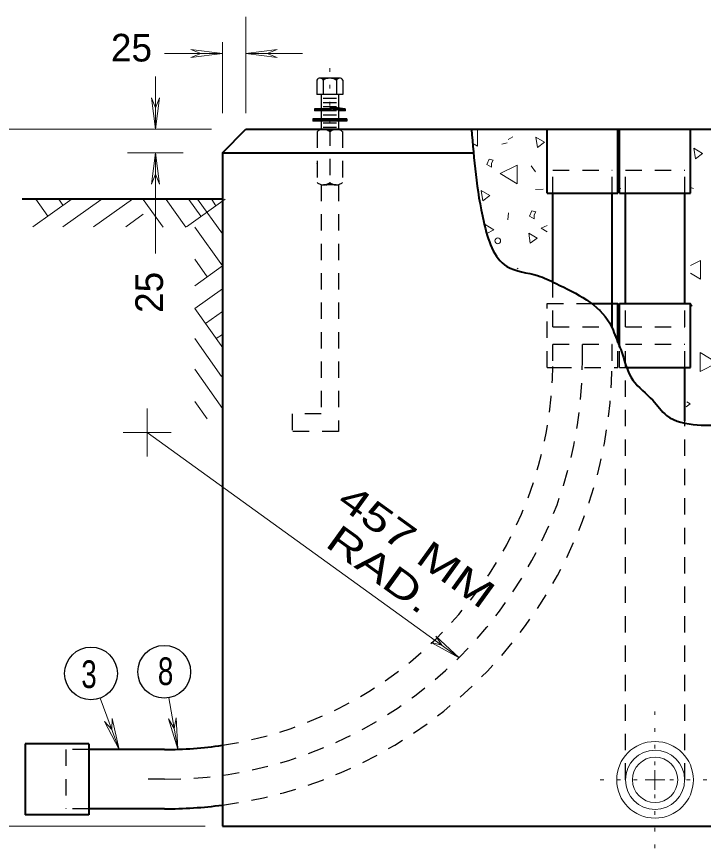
# Model space of a CAD drawing. Extents: x 312583 to 312854, y 144419 to 144597.
# Drawn here: x 312734.56 to 312753.44, y 144519.54 to 144542.49 of the extents above; entities that cross this region are included whole.
import ezdxf

# ---------------------------------------------------------------- set-up
doc = ezdxf.new("R2010")
doc.units = 0
doc.header["$LTSCALE"] = 0.3
doc.linetypes.add('DOTTED', pattern=[1.5, 0.3, -1.2])
doc.linetypes.add('SHORT_DASHED', pattern=[2.7, 1.5, -1.2])
doc.layers.add('1', color=7, linetype='Continuous', lineweight=25)
doc.layers.add('2', color=7, linetype='Continuous', lineweight=13)

msp = doc.modelspace()

# ---------------------------------------------------------------- linework, layer by layer
at = {"layer": '1', "linetype": 'DOTTED', "lineweight": 13}
msp.add_line((312743.1754, 144541.0728), (312743.1754, 144539.3938), dxfattribs=at)
at = {"layer": '1'}
for p, q in [((312742.815, 144540.7431), (312742.815, 144540.3521)), ((312743.4437, 144540.8044), (312742.907, 144540.8044)), ((312742.9914, 144540.7431), (312742.9914, 144540.3521)), ((312743.3517, 144540.7431), (312743.3517, 144540.3521)), ((312743.528, 144540.7431), (312743.528, 144540.3521)), ((312743.528, 144540.3521), (312742.815, 144540.3521)), ((312742.93, 144540.3521), (312742.93, 144539.3938)), ((312743.3517, 144540.2371), (312742.9914, 144540.2371)), ((312743.413, 144540.3521), (312743.413, 144539.3938)), ((312743.3517, 144540.1221), (312742.9914, 144540.1221)), ((312743.3517, 144540.0148), (312742.9914, 144540.0148)), ((312742.7537, 144539.9534), (312742.7537, 144539.8998)), ((312743.1907, 144539.9534), (312742.7537, 144539.9534)), ((312743.206, 144539.8998), (312742.7537, 144539.8998)), ((312743.3517, 144539.8998), (312742.9914, 144539.8998)), ((312743.3517, 144539.7848), (312742.9914, 144539.7848)), ((312743.5894, 144539.9534), (312743.5894, 144539.8998)), ((312743.643, 144539.6774), (312742.7, 144539.6774)), ((312742.7, 144539.6774), (312742.7, 144539.6161)), ((312743.643, 144539.6621), (312742.7, 144539.6621)), ((312743.643, 144539.6468), (312742.7, 144539.6468)), ((312743.643, 144539.6314), (312742.7, 144539.6314)), ((312743.643, 144539.6161), (312742.7, 144539.6161)), ((312743.3517, 144539.5624), (312742.9914, 144539.5624)), ((312743.643, 144539.6774), (312743.643, 144539.6161)), ((312743.3517, 144539.4474), (312742.9914, 144539.4474))]:
    msp.add_line(p, q, dxfattribs=at)
at = {"layer": '1', "lineweight": 40}
for p, q in [((312740.216, 144538.7498), (312740.86, 144539.3938)), ((312740.86, 144539.3938), (312771.5267, 144539.3938)), ((312749.1477, 144537.6381), (312749.1477, 144539.3938)), ((312751.095, 144537.6381), (312751.095, 144539.3938)), ((312751.141, 144537.6381), (312751.141, 144539.3938)), ((312753.0884, 144537.6381), (312753.0884, 144539.3938)), ((312740.216, 144538.7498), (312740.216, 144520.2271)), ((312740.216, 144538.7498), (312747.1544, 144538.7498)), ((312740.216, 144537.4771), (312734.7114, 144537.4771)), ((312749.1477, 144537.6381), (312751.095, 144537.6381)), ((312749.3087, 144535.2231), (312749.3087, 144537.6381)), ((312750.934, 144533.9581), (312750.934, 144537.6381)), ((312751.141, 144537.6381), (312753.0884, 144537.6381)), ((312751.302, 144534.6021), (312751.302, 144537.6381)), ((312752.935, 144534.6021), (312752.935, 144537.6381)), ((312750.382, 144534.6021), (312751.095, 144534.6021)), ((312751.095, 144533.5288), (312751.095, 144534.6021)), ((312751.141, 144534.6021), (312753.0884, 144534.6021)), ((312751.141, 144533.4061), (312751.141, 144534.6021)), ((312753.0884, 144532.8464), (312753.0884, 144534.6021)), ((312751.3634, 144532.8464), (312753.0884, 144532.8464)), ((312752.935, 144531.3744), (312752.935, 144532.8464)), ((312736.5437, 144522.4964), (312734.788, 144522.4964)), ((312734.788, 144522.4964), (312734.788, 144520.5414)), ((312736.5437, 144522.4964), (312736.5437, 144520.5414)), ((312738.6214, 144522.3354), (312736.5437, 144522.3354)), ((312738.6214, 144520.7024), (312736.5437, 144520.7024)), ((312736.5437, 144520.5414), (312734.788, 144520.5414)), ((312740.216, 144520.2271), (312772.163, 144520.2271))]:
    msp.add_line(p, q, dxfattribs=at)
at = {"layer": '1', "linetype": 'SHORT_DASHED'}
for p, q in [((312742.8227, 144539.3324), (312742.8227, 144537.9294)), ((312743.413, 144539.3938), (312742.93, 144539.3938)), ((312743.344, 144539.3938), (312742.999, 144539.3938)), ((312743.1754, 144539.3938), (312743.1754, 144537.8681)), ((312743.5204, 144539.3324), (312743.5204, 144537.9294)), ((312742.8227, 144538.4508), (312742.8074, 144538.4431)), ((312749.3087, 144538.2744), (312750.934, 144538.2744)), ((312749.3087, 144537.6381), (312749.3087, 144538.2744)), ((312750.934, 144537.6381), (312750.934, 144538.2744)), ((312751.302, 144538.2744), (312752.935, 144538.2744)), ((312751.302, 144537.6381), (312751.302, 144538.2744)), ((312752.935, 144537.6381), (312752.935, 144538.2744)), ((312742.93, 144537.8681), (312742.93, 144531.5661)), ((312743.344, 144537.8681), (312742.999, 144537.8681)), ((312743.413, 144537.8681), (312743.413, 144531.0831)), ((312749.3087, 144533.9581), (312749.3087, 144535.2231)), ((312749.1477, 144532.8464), (312749.1477, 144534.6021)), ((312749.1477, 144534.6021), (312750.382, 144534.6021)), ((312751.302, 144533.9581), (312751.302, 144534.6021)), ((312752.935, 144533.9581), (312752.935, 144534.6021)), ((312749.3087, 144533.9581), (312750.934, 144533.9581)), ((312751.302, 144533.9581), (312752.935, 144533.9581)), ((312749.3087, 144533.4828), (312750.934, 144533.4828)), ((312749.3087, 144533.0228), (312749.3087, 144533.4828)), ((312750.1214, 144533.0228), (312750.1214, 144533.4828)), ((312750.934, 144533.0228), (312750.934, 144533.4828)), ((312751.095, 144532.8464), (312751.095, 144533.5288)), ((312751.141, 144532.8464), (312751.141, 144533.4061)), ((312751.302, 144533.4828), (312752.935, 144533.4828)), ((312751.302, 144532.8464), (312751.302, 144533.4828)), ((312752.935, 144532.8464), (312752.935, 144533.4828)), ((312751.141, 144532.8464), (312751.3634, 144532.8464)), ((312751.302, 144521.5074), (312751.302, 144532.8464)), ((312752.935, 144521.5074), (312752.935, 144531.3744)), ((312743.413, 144531.0831), (312742.1327, 144531.0831)), ((312735.9074, 144522.3354), (312735.9074, 144520.7024)), ((312736.5437, 144522.3354), (312735.9074, 144522.3354)), ((312738.6214, 144521.5228), (312737.962, 144521.5228)), ((312736.5437, 144520.7024), (312735.9074, 144520.7024))]:
    msp.add_line(p, q, dxfattribs=at)
at = {"layer": '1'}
for points in [[(312742.9224, 144540.8044), (312743.1294, 144540.7968), (312743.091, 144540.7968), (312743.068, 144540.7891), (312743.0297, 144540.7738), (312742.9914, 144540.7508), (312742.9837, 144540.7738), (312742.9607, 144540.7814), (312742.9377, 144540.7968), (312743.1064, 144540.7968), (312743.0604, 144540.7891), (312743.022, 144540.7738), (312742.999, 144540.7508), (312742.9684, 144540.7814), (312742.9454, 144540.7968), (312743.091, 144540.7968), (312743.0374, 144540.7814), (312742.999, 144540.7584), (312742.953, 144540.7968), (312743.0757, 144540.7968), (312742.9914, 144540.7661), (312742.9607, 144540.7891), (312743.0604, 144540.7968), (312742.9914, 144540.7661), (312742.9684, 144540.7891), (312743.045, 144540.7891), (312742.9914, 144540.7738), (312742.976, 144540.7891), (312743.022, 144540.7891), (312742.999, 144540.7738), (312742.9914, 144540.7814), (312743.0067, 144540.7814), (312742.999, 144540.7814)], [(312743.4207, 144540.8044), (312743.2137, 144540.7968), (312743.252, 144540.7968), (312743.275, 144540.7891), (312743.3134, 144540.7738), (312743.3517, 144540.7508), (312743.3594, 144540.7738), (312743.3824, 144540.7814), (312743.413, 144540.7968), (312743.2367, 144540.7968), (312743.2827, 144540.7891), (312743.321, 144540.7738), (312743.344, 144540.7508), (312743.3747, 144540.7814), (312743.3977, 144540.7968), (312743.252, 144540.7968), (312743.3057, 144540.7814), (312743.344, 144540.7584), (312743.39, 144540.7968), (312743.275, 144540.7968), (312743.3517, 144540.7661), (312743.3824, 144540.7891), (312743.2827, 144540.7968), (312743.3517, 144540.7661), (312743.3747, 144540.7891), (312743.298, 144540.7891), (312743.3517, 144540.7738), (312743.367, 144540.7891), (312743.321, 144540.7891), (312743.344, 144540.7738), (312743.3517, 144540.7814), (312743.3364, 144540.7814), (312743.3517, 144540.7814)], [(312743.5894, 144539.9534), (312743.1754, 144540.0148), (312743.206, 144539.8998)], [(312743.413, 144539.8998), (312743.5817, 144539.9074), (312743.5817, 144539.9534), (312743.183, 144540.0071), (312743.1984, 144539.9611), (312743.413, 144539.9304), (312743.4207, 144539.9074), (312743.574, 144539.9151), (312743.574, 144539.9458), (312743.1907, 144539.9994), (312743.1984, 144539.9688), (312743.4207, 144539.9304), (312743.4284, 144539.9151), (312743.5664, 144539.9228), (312743.5664, 144539.9381), (312743.206, 144539.9841), (312743.206, 144539.9764), (312743.4207, 144539.9381), (312743.436, 144539.9304), (312743.482, 144539.9228), (312743.5587, 144539.9228), (312743.2214, 144539.9764), (312743.505, 144539.9228)], [(312743.1984, 144539.9074), (312742.769, 144539.9074), (312742.769, 144539.9534), (312743.183, 144539.9458), (312743.1984, 144539.9151), (312742.769, 144539.9151), (312742.7767, 144539.9458), (312743.1754, 144539.9381), (312743.183, 144539.9228), (312742.7767, 144539.9228), (312742.7844, 144539.9304), (312742.792, 144539.9381), (312743.1754, 144539.9304), (312743.183, 144539.9228), (312742.792, 144539.9304)], [(312743.1907, 144539.9534), (312743.5894, 144539.8998), (312743.413, 144539.8998)]]:
    msp.add_lwpolyline(points, dxfattribs=at)
at = {"layer": '1', "linetype": 'SHORT_DASHED'}
for points in [[(312743.298, 144539.3861), (312743.045, 144539.3938), (312743.068, 144539.3861), (312743.0987, 144539.3784), (312743.1294, 144539.3631), (312743.1447, 144539.3554), (312743.1677, 144539.3401), (312743.1754, 144539.3324), (312743.2214, 144539.3631), (312743.2597, 144539.3784), (312743.2904, 144539.3861), (312743.0604, 144539.3861), (312743.0757, 144539.3861), (312743.0987, 144539.3784), (312743.1294, 144539.3708), (312743.1524, 144539.3554), (312743.16, 144539.3478), (312743.1754, 144539.3401), (312743.2137, 144539.3708), (312743.2597, 144539.3861), (312743.091, 144539.3861), (312743.137, 144539.3708), (312743.1677, 144539.3478), (312743.2444, 144539.3861), (312743.114, 144539.3861), (312743.1677, 144539.3478), (312743.229, 144539.3784), (312743.1217, 144539.3784), (312743.1677, 144539.3554), (312743.206, 144539.3784), (312743.137, 144539.3784), (312743.1754, 144539.3631), (312743.2137, 144539.3708), (312743.183, 144539.3554), (312743.183, 144539.3708), (312743.1754, 144539.3478), (312743.16, 144539.3708), (312743.1447, 144539.3708), (312743.137, 144539.3708)], [(312743.298, 144537.8681), (312743.045, 144537.8681), (312743.068, 144537.8758), (312743.0987, 144537.8834), (312743.1294, 144537.8911), (312743.1447, 144537.9064), (312743.1677, 144537.9218), (312743.1754, 144537.9218), (312743.2214, 144537.8911), (312743.2597, 144537.8758), (312743.2904, 144537.8681), (312743.0604, 144537.8681), (312743.0757, 144537.8681), (312743.0987, 144537.8758), (312743.1294, 144537.8834), (312743.1524, 144537.8988), (312743.16, 144537.9064), (312743.1754, 144537.9218), (312743.2137, 144537.8911), (312743.2597, 144537.8758), (312743.091, 144537.8681), (312743.137, 144537.8834), (312743.1677, 144537.9064), (312743.2444, 144537.8758), (312743.114, 144537.8758), (312743.1677, 144537.9141), (312743.229, 144537.8758), (312743.1217, 144537.8758), (312743.1677, 144537.8988), (312743.206, 144537.8834), (312743.137, 144537.8834), (312743.1754, 144537.8911), (312743.2137, 144537.8834), (312743.183, 144537.8988), (312743.183, 144537.8834), (312743.1754, 144537.9064), (312743.16, 144537.8911), (312743.1447, 144537.8911), (312743.137, 144537.8834)], [(312749.1477, 144532.8464), (312749.37, 144532.8464), (312751.095, 144532.8464)], [(312742.93, 144531.5661), (312742.1327, 144531.5661), (312742.1327, 144531.0831)]]:
    msp.add_lwpolyline(points, dxfattribs=at)
at = {"layer": '1', "lineweight": 13}
for radius in [1.0542, 0.8146, 0.6232]:
    msp.add_circle((312752.1166, 144521.5036), radius, dxfattribs=at)
at = {"layer": '1'}
for centre, radius, start, end in [((312742.9029, 144540.7029), 0.0993, 25.60064, 154.39936), ((312743.1715, 144540.4896), 0.3126, 55.04559, 124.95441), ((312743.4402, 144540.7029), 0.0993, 25.60064, 154.39936)]:
    msp.add_arc(centre, radius, start, end, dxfattribs=at)
at = {"layer": '1', "linetype": 'SHORT_DASHED'}
for centre, radius, start, end in [((312742.9968, 144539.1204), 0.272, 50.00693, 129.99306), ((312743.3464, 144539.1204), 0.272, 50.00694, 129.99307), ((312742.9968, 144538.1378), 0.272, 230.00694, 309.99307), ((312743.3464, 144538.1378), 0.272, 230.00693, 309.99306), ((312738.6201, 144533.0196), 11.5, 270, 0), ((312738.6201, 144533.0196), 10.6854, 278.59661, 0), ((312738.6201, 144533.0196), 12.3146, 277.45236, 0)]:
    msp.add_arc(centre, radius, start, end, dxfattribs=at)
at = {"layer": '1', "lineweight": 40}
for radius, end in [(10.6854, 278.59661), (12.3146, 277.45236)]:
    msp.add_arc((312738.6201, 144533.0196), radius, 270, end, dxfattribs=at)
msp.add_spline([(312747.07, 144539.3938), (312747.4074, 144536.8408), (312748.0437, 144535.6218), (312748.887, 144535.3688), (312749.393, 144535.1541), (312750.8727, 144534.0578), (312751.0874, 144533.5518), (312751.1717, 144533.3371), (312751.509, 144532.4938), (312752.0534, 144531.9418), (312752.4367, 144531.5201), (312753.28, 144531.2671), (312754.085, 144531.2671), (312755.4727, 144531.3974), (312756.1474, 144531.4818), (312757.5044, 144531.1828), (312758.3477, 144531.0141), (312759.8657, 144531.1828), (312760.9237, 144531.1444), (312762.2347, 144531.3974), (312763.2007, 144532.0261), (312764.0057, 144532.7084), (312764.5117, 144534.1421), (312764.7264, 144534.5638), (312764.8107, 144535.1158), (312764.7264, 144535.8288), (312764.7264, 144536.5878), (312764.8107, 144537.3084), (312765.2324, 144538.2821), (312764.7647, 144538.9568), (312764.9334, 144539.3938)], degree=3, dxfattribs=at)
at = {"layer": '2'}
for p, q in [((312740.86, 144539.8384), (312740.86, 144542.4911)), ((312739.3497, 144541.5864), (312739.6257, 144541.4791)), ((312740.216, 144541.4791), (312739.3497, 144541.5864)), ((312740.216, 144539.8384), (312740.216, 144541.7934)), ((312740.86, 144541.4791), (312741.7264, 144541.5864)), ((312741.7264, 144541.5864), (312741.4504, 144541.4791)), ((312738.6214, 144541.4791), (312740.216, 144541.4791)), ((312739.3497, 144541.3718), (312739.6257, 144541.4791)), ((312740.216, 144541.4791), (312739.3497, 144541.3718)), ((312740.86, 144541.4791), (312742.424, 144541.4791)), ((312740.86, 144541.4791), (312741.7264, 144541.3718)), ((312741.7264, 144541.3718), (312741.4504, 144541.4791)), ((312738.376, 144539.3938), (312738.376, 144540.8428)), ((312738.2687, 144540.2601), (312738.376, 144539.9841)), ((312738.376, 144539.3938), (312738.2687, 144540.2601)), ((312738.4834, 144540.2601), (312738.376, 144539.9841)), ((312738.376, 144539.3938), (312738.4834, 144540.2601)), ((312739.917, 144539.3938), (312731.0007, 144539.3938)), ((312747.1314, 144539.3938), (312747.0777, 144539.3631)), ((312747.231, 144538.9261), (312747.231, 144539.3938)), ((312748.0744, 144539.1178), (312748.2047, 144539.1868)), ((312747.139, 144538.9874), (312747.231, 144538.9261)), ((312747.9057, 144538.9874), (312748.0514, 144539.0181)), ((312739.1384, 144538.7498), (312737.607, 144538.7498)), ((312738.376, 144538.7498), (312738.2687, 144537.8835)), ((312738.376, 144535.9821), (312738.376, 144538.7498)), ((312738.376, 144538.7498), (312738.4834, 144537.8835)), ((312748.7107, 144538.3894), (312748.8334, 144538.2284)), ((312738.2687, 144537.8835), (312738.376, 144538.1595)), ((312738.4834, 144537.8835), (312738.376, 144538.1595)), ((312748.8257, 144537.7378), (312749.0404, 144537.7454)), ((312751.095, 144537.7914), (312751.1794, 144537.7684)), ((312753.0884, 144537.7914), (312753.1727, 144537.7684)), ((312735.0027, 144536.7104), (312736.0837, 144537.4848)), ((312735.087, 144537.4771), (312735.4167, 144537.0094)), ((312735.7157, 144537.4771), (312735.8307, 144537.3084)), ((312735.8307, 144536.7104), (312736.8734, 144537.4541)), ((312736.674, 144536.7104), (312737.7474, 144537.4771)), ((312738.0387, 144537.4618), (312738.583, 144536.7028)), ((312738.6674, 144537.4618), (312739.2117, 144536.7028)), ((312739.227, 144536.7104), (312740.2927, 144537.4771)), ((312739.296, 144537.4618), (312739.6257, 144537.0018)), ((312739.5337, 144537.4771), (312740.216, 144536.5188)), ((312739.9247, 144537.4618), (312740.0397, 144537.2931)), ((312737.5557, 144536.7104), (312738.0387, 144537.0631)), ((312748.0667, 144536.9021), (312748.0897, 144537.0938)), ((312739.457, 144536.7028), (312740.216, 144535.6371)), ((312739.457, 144535.8211), (312739.802, 144535.3381)), ((312740.216, 144535.6371), (312739.457, 144535.0928)), ((312748.3504, 144535.5758), (312748.3274, 144535.5604)), ((312753.0884, 144535.4378), (312753.372, 144535.2691)), ((312749.3087, 144535.2844), (312749.3164, 144535.2001)), ((312740.216, 144535.0084), (312739.457, 144534.4641)), ((312739.457, 144534.4641), (312740.2314, 144533.3831)), ((312751.095, 144534.6021), (312751.1487, 144534.5331)), ((312753.0884, 144534.6021), (312753.142, 144534.5331)), ((312740.216, 144534.3798), (312739.7484, 144534.0501)), ((312750.612, 144534.4411), (312750.612, 144534.4104)), ((312739.457, 144533.6361), (312740.193, 144532.5934)), ((312740.216, 144533.7511), (312740.0474, 144533.6361)), ((312739.457, 144532.7928), (312740.216, 144531.7194)), ((312738.146, 144531.0524), (312738.146, 144531.7118)), ((312739.457, 144531.9111), (312739.802, 144531.4281)), ((312738.146, 144531.0524), (312737.4867, 144531.0524)), ((312746.725, 144524.8578), (312738.146, 144531.0524)), ((312738.146, 144531.0524), (312738.8054, 144531.0524)), ((312738.146, 144531.0524), (312738.146, 144530.3931)), ((312745.9584, 144525.2794), (312746.2497, 144525.2104)), ((312746.725, 144524.8578), (312745.9584, 144525.2794)), ((312746.0887, 144525.4558), (312746.2497, 144525.2104)), ((312746.725, 144524.8578), (312746.0887, 144525.4558)), ((312736.8504, 144523.7461), (312737.3794, 144522.3354)), ((312738.744, 144523.7614), (312738.9894, 144522.3431)), ((312738.9434, 144523.2094), (312738.8897, 144522.9181)), ((312738.9894, 144522.3431), (312738.9434, 144523.2094)), ((312736.973, 144523.1098), (312737.1724, 144522.8874)), ((312737.3794, 144522.3354), (312736.973, 144523.1098)), ((312737.18, 144523.1864), (312737.1724, 144522.8874)), ((312737.3794, 144522.3354), (312737.18, 144523.1864)), ((312738.7364, 144523.1788), (312738.8897, 144522.9181)), ((312738.9894, 144522.3431), (312738.7364, 144523.1788)), ((312752.1147, 144521.4998), (312752.1147, 144521.7681)), ((312752.1147, 144521.4998), (312751.8464, 144521.4998)), ((312752.1147, 144521.4998), (312752.383, 144521.4998)), ((312752.1147, 144521.4998), (312752.1147, 144521.2314)), ((312739.7407, 144520.2271), (312731.0007, 144520.2271))]:
    msp.add_line(p, q, dxfattribs=at)
at = {"layer": '2', "linetype": 'DOTTED'}
for p, q in [((312752.1147, 144521.9061), (312752.1147, 144523.6081)), ((312751.624, 144521.4998), (312750.5584, 144521.4998)), ((312752.521, 144521.4998), (312754.1617, 144521.4998)), ((312752.1147, 144521.1011), (312752.1147, 144519.5371))]:
    msp.add_line(p, q, dxfattribs=at)
at = {"layer": '2'}
for points in [[(312748.887, 144538.8954), (312749.0787, 144539.0411), (312748.841, 144539.1791)], [(312753.2264, 144538.5811), (312753.418, 144538.7268), (312753.188, 144538.8724)], [(312747.622, 144538.4584), (312747.668, 144538.5428), (312747.553, 144538.5734), (312747.4917, 144538.4278), (312747.622, 144538.3511)], [(312748.3274, 144537.8911), (312748.3274, 144538.4048), (312747.8597, 144538.1748)], [(312747.3767, 144537.4311), (312747.5684, 144537.5768), (312747.3384, 144537.7148)], [(312748.795, 144537.0401), (312748.841, 144537.1244), (312748.726, 144537.1551), (312748.6647, 144537.0018), (312748.795, 144536.9328)], [(312748.68, 144536.2581), (312748.8717, 144536.4038), (312748.6417, 144536.5418)], [(312753.3567, 144533.2528), (312753.3567, 144532.7314), (312753.8244, 144532.9691)]]:
    msp.add_lwpolyline(points, close=True, dxfattribs=at)
for points in [[(312747.4764, 144536.5188), (312747.6834, 144536.6261), (312747.4457, 144536.7718)], [(312749.1477, 144536.7488), (312748.9867, 144536.6721), (312749.1477, 144536.5724)], [(312753.372, 144535.2691), (312753.372, 144535.7828), (312753.0884, 144535.6448)], [(312752.9734, 144531.7654), (312753.0807, 144531.8421), (312752.9887, 144531.8958)]]:
    msp.add_lwpolyline(points, dxfattribs=at)
msp.add_circle((312747.7915, 144536.3268), 0.0784, dxfattribs=at)
at = {"layer": '2', "lineweight": 25}
for centre in [(312736.6018, 144524.4291), (312738.6175, 144524.4744)]:
    msp.add_circle(centre, 0.7254, dxfattribs=at)

# ---------------------------------------------------------------- texts
at = {"layer": '2'}
msp.add_text('25', height=0.76, dxfattribs=at).set_placement((312737.1498, 144541.2591))
msp.add_text('25', height=0.76, rotation=90, dxfattribs=at).set_placement((312738.5819, 144534.3431))
at = {"layer": '2', "width": 1.35}
for s, p in [('457 MM ', (312743.331, 144529.075)), (' RAD.', (312742.7022, 144528.168))]:
    msp.add_text(s, height=0.76, rotation=324.186, dxfattribs=at).set_placement(p)
at = {"layer": '2', "width": 0.75}
for s, p in [('8', (312738.4419, 144524.1098)), ('3', (312736.3358, 144524.0279))]:
    msp.add_text(s, height=0.76, dxfattribs=at).set_placement(p)

doc.saveas('drawing.dxf')
